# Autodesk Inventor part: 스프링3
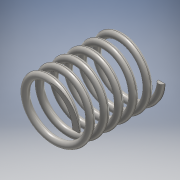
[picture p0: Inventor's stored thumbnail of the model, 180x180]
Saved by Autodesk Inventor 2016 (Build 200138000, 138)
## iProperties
Created: 2019-07
Part Number: 스프링3
Material: 강철, 탄소
Document SubType Name: Modeling
Designer: 602-01
Density: 7.85 g/cm^3
Appearance: 반연마
Mass: 7.77017 g
Surface Area: 20.0872 cm^2
Volume: 0.989831 cm^3
Author: 602-01
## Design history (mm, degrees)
sketch "스케치1"
  geometry: L1 (0, 0)-(8.5, 0); L2 (8.5, 0)-(8.5, 25.33); L3 (8.5, 25.33)-(0, 25.33); L4 (0, 25.33)-(0, 0); C1 r 1 at (8.5, 0)
  constraints: 8 end point, 2 parallel, 1 centre point, 1 coincident, 1 horizontal, 1 perpendicular
  dimensions: "d0" = 17 diameter of L2 L4; "d1" = 25.33013 distance between parallel lines of L1 L3 (derived); "d2" = 2 diameter of C1
feature "코일1" sketch "스케치1" pitch "d3" = 10; turns "d5" = 6; dims "d4" = 25.33013 (= d1), "d6" = 0, angle "d7" = 90 deg, angle "d8" = 90 deg, "d9" = 0, "d10" = 0
sketch "스케치2"
  geometry: L1 (-7.5, 0)-(-9.5, 0) reference; 1 further point
  constraints: 1 horizontal alignment
extrude "돌출1" cut sketch "스케치2" distance "d11" = 10; taper "d12" = 0 deg
node "작업 평면1"
sketch "스케치3"
  geometry: L1 (-1, 0)-(1, 0) reference; 1 further point
  constraints: 1 horizontal alignment
extrude "돌출2" cut sketch "스케치3" distance "d14" = 10; taper "d15" = 0 deg
node "솔리드1"
node "절단 모서리 투영1"
node "절단 모서리 투영2"
other parameters: "d13" = 90 deg
